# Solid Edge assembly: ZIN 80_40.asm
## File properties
Title: Zylinder
Author: bmolnar
Template: iso metric assembly.asm
Last saved by: bmolnar
Revision: 16
Application: Solid Edge
Username: bmolnar
Dokumentum tartalom típus: 1
Document Number: ZIN 80/40
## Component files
Kit_1.par
Kit_2.par
Kolbenstange.par
Profilrohr.par
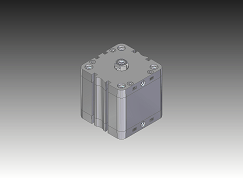
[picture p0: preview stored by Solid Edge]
